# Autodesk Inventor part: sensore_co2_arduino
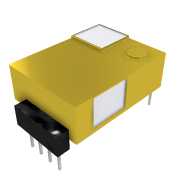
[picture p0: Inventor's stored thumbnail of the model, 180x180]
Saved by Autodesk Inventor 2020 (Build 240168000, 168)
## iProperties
Created: 2020-12
Part Number: sensore_co2_arduino
Material: Generico
Document SubType Name: Modeling
Designer: admin
Density: 1 g/cm^3
Appearance: Default
Author: admin
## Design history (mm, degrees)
node "Annotazioni"
  node "Quota lineare 1" dims "d51" = 26.8 (derived)
  node "Quota lineare 2" dims "d54" = 8.7 (derived)
  node "Quota lineare 4" dims "d60" = 10.4 (derived)
  node "Quota lineare 5" dims "d62" = 9.3 (derived)
  node "Quota lineare 6" dims "d65" = 8.7 (derived)
  node "Quota lineare 7" dims "d68" = 5 (derived)
  node "Quota lineare 8" dims "d71" = 13 (derived)
  node "Quota lineare 9" dims "d74" = 19.4 (derived)
  node "Quota lineare 10" dims "d77" = 9.6 (derived)
  node "Quota lineare 11" dims "d80" = 9.60469 (derived)
  node "Quota diametro 1" dims "d82" = 5.1 (derived)
  node "Quota lineare 12" dims "d85" = 4.3 (derived)
  node "Quota lineare 13" dims "d86" = 2.5 (derived)
  node "Quota lineare 14" dims "d87" = 2.5 (derived)
  node "Quota lineare 15" dims "d89" = 4.7 (derived)
  node "Quota lineare 16" dims "d92" = 14.2 (derived)
  node "Quota lineare 17" dims "d95" = 5 (derived)
  node "Quota lineare 18" dims "d98" = 2 (derived)
  node "Quota lineare 19" dims "d99" = 2.5 (derived)
  node "Quota lineare 20" dims "d100" = 2 (derived)
sketch "Schizzo1"
  geometry: L1 (0, 0)-(20, 0); L2 (20, 0)-(20, -26.8); L3 (20, -26.8)-(0, -26.8); L4 (0, -26.8)-(0, 0)
  constraints: 8 end point, 2 parallel, 1 horizontal, 1 perpendicular
  dimensions: "d0" = 20 distance of L2.end L3.end; "d1" = 26.8 distance of L1.end L2.end
extrude "Estrusione1" new body sketch "Schizzo1" distance "d2" = 8.7; taper "d3" = 0 deg
sketch "Schizzo2"
  geometry: L1 (-20, 0)-(0, 0) reference; L2 (-2, 0)-(-15, 0); L3 (-15, 0)-(-15, 3); L4 (-15, 3)-(-2, 3); L5 (-2, 3)-(-2, 0); L6 (0, -26.8)-(-20, -26.8) reference; L7 (-2, -26.8)-(-16.2, -26.8); L8 (-16.2, -26.8)-(-16.2, -29.8); L9 (-16.2, -29.8)-(-2, -29.8); L10 (-2, -29.8)-(-2, -26.8); L11 (0, 0)-(0, -26.8) reference; 2 further points
  constraints: 16 end point, 4 parallel, 2 horizontal, 2 perpendicular, 2 point on line
  dimensions: "d4" = 13 distance of L3.end L4.end; "d5" = 3 distance of L2.end L3.end; "d6" = 14.2 distance of L9.end L8.end; "d7" = 3 distance of L8.end L7.end; "d8" = 2 distance between parallel lines of L11 L10; "d9" = 2 distance between parallel lines of L11 L5
extrude "Estrusione2" join sketch "Schizzo2" distance "d10" = 2.5; taper "d11" = 0 deg
sketch "Schizzo3"
  geometry: L1 (-2, 3)-(-2, 0) reference; L2 (-20, 0)-(-15, 0) reference; L3 (-2, 3)-(-15, 3); L4 (-15, 3)-(-15, 0); L5 (-15, 0)-(-2, 0); L6 (-2, 0)-(-2, 3); L7 (0, -26.8)-(-2, -26.8) reference; L8 (-16.2, -29.8)-(-16.2, -26.8) reference; L9 (-2, -26.8)-(-16.2, -26.8); L10 (-16.2, -26.8)-(-16.2, -29.8); L11 (-16.2, -29.8)-(-2, -29.8); L12 (-2, -29.8)-(-2, -26.8); 3 further points
  constraints: 16 end point, 4 parallel, 2 horizontal, 2 perpendicular
extrude "Estrusione3" join sketch "Schizzo3" distance "d12" = 2.5; taper "d13" = 0 deg
sketch "Schizzo4" dims "d21" = 10, "d30" = 10
  geometry: L1 (-3.125, 1.94)-(-3.625, 1.94); L2 (-3.625, 1.94)-(-3.625, 1.44); L3 (-3.625, 1.44)-(-3.125, 1.44); L4 (-3.125, 1.44)-(-3.125, 1.94); L5 (-6.125, 1.94)-(-6.625, 1.94); L6 (-6.625, 1.94)-(-6.625, 1.44); L7 (-6.625, 1.44)-(-6.125, 1.44); L8 (-6.125, 1.44)-(-6.125, 1.94); L9 (-9.125, 1.94)-(-9.625, 1.94); L10 (-9.625, 1.94)-(-9.625, 1.44); L11 (-9.625, 1.44)-(-9.125, 1.44); L12 (-9.125, 1.44)-(-9.125, 1.94); L13 (-12.125, 1.94)-(-12.625, 1.94); L14 (-12.625, 1.94)-(-12.625, 1.44); L15 (-12.625, 1.44)-(-12.125, 1.44); L16 (-12.125, 1.44)-(-12.125, 1.94); L17 (-3.125, -27.923)-(-3.625, -27.923); L18 (-3.625, -27.923)-(-3.625, -28.423); L19 (-3.625, -28.423)-(-3.125, -28.423); L20 (-3.125, -28.423)-(-3.125, -27.923); L21 (-5.875, -27.923)-(-6.375, -27.923); L22 (-6.375, -27.923)-(-6.375, -28.423); L23 (-6.375, -28.423)-(-5.875, -28.423); L24 (-5.875, -28.423)-(-5.875, -27.923); L25 (-8.625, -27.923)-(-9.125, -27.923); L26 (-9.125, -27.923)-(-9.125, -28.423); L27 (-9.125, -28.423)-(-8.625, -28.423); L28 (-8.625, -28.423)-(-8.625, -27.923); L29 (-11.375, -27.923)-(-11.875, -27.923); L30 (-11.875, -27.923)-(-11.875, -28.423); L31 (-11.875, -28.423)-(-11.375, -28.423); L32 (-11.375, -28.423)-(-11.375, -27.923); L33 (-14.125, -27.923)-(-14.625, -27.923); L34 (-14.625, -27.923)-(-14.625, -28.423); L35 (-14.625, -28.423)-(-14.125, -28.423); L36 (-14.125, -28.423)-(-14.125, -27.923); 1 further point
  constraints: 72 end point, 4 horizontal, 4 parallel, 2 collinear, 2 perpendicular, 54 other
  dimensions: "d14" = 0.5 distance of L3.end L2.end; "d15" = 0.5 distance of L2.end L1.end; "d18" = 3 distance of L1.start L5.start; "d23" = 0.5 distance of L19.end L18.end; "d24" = 0.5 distance of L18.end L17.end; "d27" = 2.75 distance of L17.end L21.end
extrude "Estrusione4" join sketch "Schizzo4" distance "d32" = 5.5; taper "d33" = 0 deg
sketch "Schizzo5"
  geometry: L1 (0, 8.7)-(26.8, 8.7) reference; L2 (26.8, 0)-(0, 0) reference; L3 (4, 8.7)-(13.6, 8.7); L4 (13.6, 8.7)-(13.6, 1.075); L5 (4, 1.075)-(4, 8.7); L6 (0, 0)-(0, 8.7) reference; L7 (4.3, 8.4)-(13.321, 8.4); L8 (13.321, 8.4)-(13.321, 1.375); L9 (4.3, 1.375)-(4.3, 8.4); L10 (4.3, 1.375)-(13.321, 1.375); L11 (4, 1.075)-(13.6, 1.075); L12 (13.6, 0)-(13.321, 0); L13 (4.3, 0)-(4, 0); 1 further point
  constraints: 20 end point, 5 parallel, 5 point on line, 3 perpendicular, 1 horizontal
  dimensions: "d35" = 4 distance between parallel lines of L6 L5; "d36" = 0.3 distance between parallel lines of L5 L9; "d102" = 0.3 distance between parallel lines of L10 L11; "d106" = 9.6 distance between parallel lines of L4 L5
extrude "Estrusione5" cut sketch "Schizzo5" distance "d37" = 0.2; taper "d38" = 0 deg
sketch "Schizzo6"
  geometry: L1 (-20, 26.8)-(-20, 0) reference; L2 (-20, 26.8)-(-10.4, 26.8); L3 (-10.4, 26.8)-(-10.4, 17.2); L4 (-10.4, 17.2)-(-20, 17.2); L5 (-20, 17.2)-(-20, 26.8); C1 r 2.25 at (-4.138, 21.8); 2 further points
  constraints: 8 end point, 2 parallel, 1 centre point, 1 horizontal, 1 perpendicular
  dimensions: "d39" = 9.6 distance of L3.end L4.end; "d40" = 9.6 distance of L2.end L3.end; "d43" = 4.5 diameter of C1
extrude "Estrusione6" join sketch "Schizzo6" distance "d41" = 0.6; taper "d42" = 0 deg
fillet "Raccordo1" dims "d44" = 0.3
sketch "Schizzo7"
  geometry: L1 (-20, 26.8)-(-20, 17.2) reference; L2 (-10.4, 17.5)-(-20, 17.5) reference; L3 (-10.4, 26.8)-(-20, 26.8) reference; L4 (-10.4, 17.2)-(-10.4, 26.8) reference; L5 (-19.8, 17.7)-(-19.8, 26.5); L6 (-19.7, 26.6)-(-10.6, 26.6); L7 (-10.6, 26.6)-(-10.6, 17.7); L8 (-10.6, 17.7)-(-19.8, 17.7); A1 r 0.3 centre (-19.7, 26.5) between (-19.7, 26.8) and (-20, 26.5) reference; A2 r 0.1 centre (-19.7, 26.5) between (-19.7, 26.6) and (-19.8, 26.5); 1 further point
  constraints: 8 end point, 2 point on circle, 1 centre point, 4 other
  dimensions: "d45" = 0.2 distance between parallel lines of L1 L5
extrude "Estrusione7" cut sketch "Schizzo7" distance "d46" = 0.2; taper "d47" = 0 deg
fillet "Raccordo2" dims "d48" = 0.3
sketch "Schizzo8"
  geometry: L1 (4.3, 1.375)-(4.3, 8.4) reference; L2 (13.321, 1.375)-(4.3, 1.375) reference; L3 (13.321, 8.4)-(13.321, 1.375) reference; L4 (4.3, 8.4)-(13.321, 8.4) reference; L5 (4, 8.7)-(4, 1.075); L6 (4, 1.075)-(13.621, 1.075); L7 (13.621, 1.075)-(13.621, 8.7); L8 (13.621, 8.7)-(4, 8.7); 1 further point
  constraints: 8 end point, 3 other
  dimensions: "d103" = 0.3 distance between parallel lines of L1 L5
extrude "Estrusione8" join sketch "Schizzo8" distance "d104" = 0.1; taper "d105" = 0 deg
node "Solido1"
node "Linea chiusa proiettata1"
other parameters: "d49" = 5.75238 (derived), "d50" = 5.80795 (derived), "d52" = 7.55239 (derived), "d53" = 8.79132 (derived), "d58" = 2.40594 (derived), "d59" = 8.99145 (derived), "d61" = 8.29709 (derived), "d63" = 0.44375 (derived), "d64" = 0.9674 (derived), "d66" = 0 (derived), "d69" = 7.35386 (derived), "d70" = 4.78023 (derived), "d72" = 0 (derived), "d75" = 2.94909 (derived), "d76" = 9.16331 (derived), "d78" = 9.20651 (derived), "d79" = 1.34513 (derived), "d81" = 44.96383 (derived), "d83" = 9.37243 (derived), "d84" = 8.00447 (derived), "d88" = 2.90541 (derived), "d90" = 4.71216 (derived), "d91" = 6.79465 (derived), "d93" = 6.38114 (derived), "d94" = 4.40463 (derived), "d96" = 3.01267 (derived), "d97" = 7.54656 (derived)
